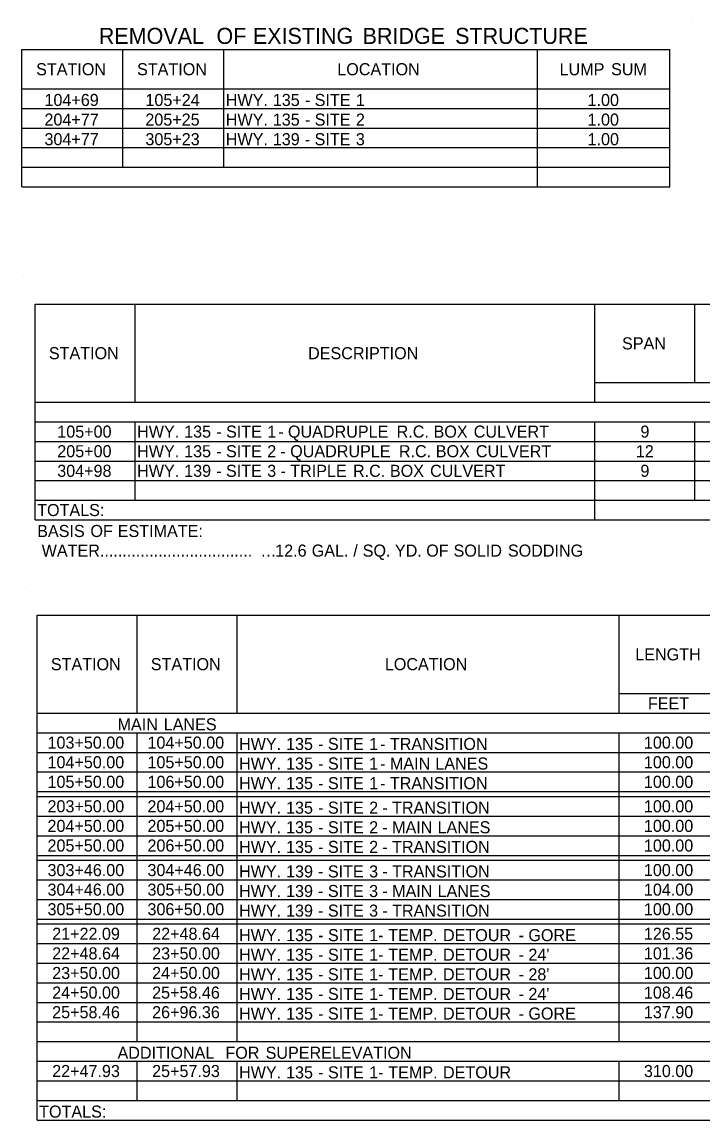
# Model space of a CAD drawing. Extents: x 1955554 to 1962042, y 565952 to 568347.
# Drawn here: x 1958686 to 1959025, y 566455 to 567001 of the extents above; entities that cross this region are included whole.
import ezdxf

# ---------------------------------------------------------------- set-up
doc = ezdxf.new("R2010")
doc.units = 0
doc.layers.add('Default', color=7, linetype='Continuous')
doc.layers.add('R_Border', color=7, linetype='Continuous')

msp = doc.modelspace()

# ---------------------------------------------------------------- linework, layer by layer
at = {"layer": 'Default'}
for p, q in [((1958686.27, 566987.49), (1959008.51, 566987.49)), ((1958686.27, 566919.24), (1958686.27, 566987.49)), ((1958686.27, 566919.24), (1958686.27, 566987.49)), ((1958736.48, 566928.99), (1958736.48, 566987.49)), ((1958786.7, 566928.99), (1958786.7, 566987.49)), ((1958942.7, 566919.24), (1958942.7, 566987.49)), ((1959008.51, 566919.24), (1959008.51, 566987.49)), ((1959008.51, 566919.24), (1959008.51, 566987.49)), ((1958686.27, 566967.99), (1959008.51, 566967.99)), ((1958736.48, 566928.99), (1958736.48, 566967.99)), ((1958786.7, 566928.99), (1958786.7, 566967.99)), ((1958942.7, 566928.99), (1958942.7, 566967.99)), ((1958686.27, 566958.24), (1959008.51, 566958.24)), ((1958942.7, 566958.24), (1959008.51, 566958.24)), ((1958686.27, 566948.49), (1959008.51, 566948.49)), ((1958686.27, 566938.74), (1959008.51, 566938.74)), ((1958686.27, 566928.99), (1958942.7, 566928.99)), ((1958686.27, 566928.99), (1958942.7, 566928.99)), ((1958942.7, 566928.99), (1959008.51, 566928.99)), ((1958686.27, 566919.24), (1959008.51, 566919.24)), ((1958687.02, 566874.57), (1958687.02, 566874.57)), ((1958692.87, 566860.92), (1959581.1, 566860.92)), ((1958692.87, 566753.67), (1958692.87, 566860.92)), ((1958692.87, 566753.67), (1958692.87, 566860.92)), ((1958742.6, 566812.17), (1958742.6, 566860.92)), ((1958971.24, 566812.17), (1958971.24, 566860.92)), ((1959020.96, 566821.92), (1959020.96, 566860.92)), ((1958971.24, 566821.92), (1959369.04, 566821.92)), ((1958692.87, 566812.17), (1959581.1, 566812.17)), ((1958692.87, 566802.42), (1959581.1, 566802.42)), ((1958742.6, 566763.42), (1958742.6, 566802.42)), ((1958742.6, 566763.42), (1958742.6, 566802.42)), ((1958971.24, 566753.67), (1958971.24, 566802.42)), ((1959020.96, 566763.42), (1959020.96, 566802.42)), ((1959020.96, 566763.42), (1959020.96, 566802.42)), ((1958692.87, 566792.67), (1959581.1, 566792.67)), ((1958692.87, 566782.92), (1959581.1, 566782.92)), ((1958692.87, 566773.17), (1959581.1, 566773.17)), ((1958692.87, 566763.42), (1959369.04, 566763.42)), ((1958742.6, 566763.42), (1958971.24, 566763.42)), ((1958971.24, 566763.42), (1959369.04, 566763.42)), ((1958692.87, 566753.67), (1959581.1, 566753.67)), ((1958688, 566719.93), (1958688, 566719.93)), ((1958693.85, 566706.28), (1960133.43, 566706.28)), ((1958693.85, 566455.22), (1958693.85, 566706.28)), ((1958693.85, 566455.22), (1958693.85, 566706.28)), ((1958743.57, 566657.53), (1958743.57, 566706.28)), ((1958793.3, 566657.53), (1958793.3, 566706.28)), ((1958983.42, 566657.53), (1958983.42, 566706.28)), ((1958983.42, 566667.28), (1959033.15, 566667.28)), ((1958693.85, 566657.53), (1960133.43, 566657.53)), ((1958693.85, 566647.78), (1960133.43, 566647.78)), ((1958743.57, 566494.22), (1958743.57, 566647.78)), ((1958743.57, 566494.22), (1958743.57, 566647.78)), ((1958793.3, 566494.22), (1958793.3, 566647.78)), ((1958793.3, 566494.22), (1958793.3, 566647.78)), ((1958983.42, 566494.22), (1958983.42, 566647.78)), ((1958983.42, 566494.22), (1958983.42, 566647.78)), ((1958693.85, 566638.03), (1960133.43, 566638.03)), ((1958693.85, 566628.28), (1960133.43, 566628.28)), ((1958693.85, 566618.53), (1960133.43, 566618.53)), ((1958693.85, 566616.09), (1960133.43, 566616.09)), ((1958693.85, 566606.34), (1960133.43, 566606.34)), ((1958693.85, 566596.59), (1960133.43, 566596.59)), ((1958693.85, 566586.84), (1960133.43, 566586.84)), ((1958693.85, 566584.4), (1960133.43, 566584.4)), ((1958693.85, 566574.65), (1960133.43, 566574.65)), ((1958693.85, 566564.9), (1960133.43, 566564.9)), ((1958693.85, 566555.15), (1960133.43, 566555.15)), ((1958693.85, 566552.72), (1960133.43, 566552.72)), ((1958693.85, 566542.97), (1960133.43, 566542.97)), ((1958693.85, 566533.22), (1960133.43, 566533.22)), ((1958693.85, 566523.47), (1960133.43, 566523.47)), ((1958693.85, 566513.72), (1960133.43, 566513.72)), ((1958693.85, 566503.97), (1960133.43, 566503.97)), ((1958693.85, 566494.22), (1960133.43, 566494.22)), ((1958693.85, 566494.22), (1960133.43, 566494.22)), ((1958693.85, 566484.47), (1960133.43, 566484.47)), ((1958743.57, 566464.97), (1958743.57, 566484.47)), ((1958743.57, 566464.97), (1958743.57, 566484.47)), ((1958793.3, 566464.97), (1958793.3, 566484.47)), ((1958793.3, 566464.97), (1958793.3, 566484.47)), ((1958983.42, 566464.97), (1958983.42, 566484.47)), ((1958983.42, 566464.97), (1958983.42, 566484.47)), ((1958693.85, 566474.72), (1960133.43, 566474.72)), ((1958693.85, 566464.97), (1960133.43, 566464.97)), ((1958693.85, 566455.22), (1960133.43, 566455.22))]:
    msp.add_line(p, q, dxfattribs=at)
at = {"layer": 'R_Border'}
msp.add_line((1959020.08, 567001.23), (1959020.08, 567001.23), dxfattribs=at)

# ---------------------------------------------------------------- texts
at = {"layer": 'Default'}
for s, height, p in [('REMOVAL', 8, (1958724.5, 566990.31)), (' OF', 8, (1958780.06, 566990.31)), (' EXISTING', 8, (1958798.17, 566990.31)), (' BRIDGE', 8, (1958852.77, 566990.31)), (' STRUCTURE', 8, (1958898.8, 566990.31)), ('STATION', 6, (1958693.32, 566974.74)), ('STATION', 6, (1958743.53, 566974.74)), ('LOCATION', 6, (1958843.14, 566974.74)), ('LUMP', 6, (1958953.74, 566974.74)), (' SUM', 6, (1958977.11, 566974.74)), ('104+69', 6, (1958697.47, 566959.44)), ('105+24', 6, (1958747.7, 566959.44)), ('HWY.', 6, (1958787.67, 566959.44)), (' 135', 6, (1958808.83, 566959.44)), (' SITE', 6, (1958829.66, 566959.44)), (' 1', 6, (1958850.17, 566959.44)), ('1.00', 6, (1958967.65, 566959.44)), (' -', 6, (1958824.8, 566959.44)), ('204+77', 6, (1958697.47, 566949.69)), ('205+25', 6, (1958747.66, 566949.69)), ('HWY.', 6, (1958787.67, 566949.69)), (' 135', 6, (1958808.83, 566949.69)), (' -', 6, (1958824.8, 566949.69)), (' SITE', 6, (1958829.66, 566949.69)), (' 2', 6, (1958850.17, 566949.69)), ('1.00', 6, (1958967.65, 566949.69)), ('304+77', 6, (1958697.47, 566939.94)), ('305+23', 6, (1958747.68, 566939.94)), ('HWY.', 6, (1958787.67, 566939.94)), (' 139', 6, (1958808.83, 566939.94)), (' -', 6, (1958824.76, 566939.94)), (' SITE', 6, (1958829.62, 566939.94)), (' 3', 6, (1958850.14, 566939.94)), ('1.00', 6, (1958967.65, 566939.94)), ('SPAN', 6, (1958984.79, 566838.42)), ('STATION', 6, (1958699.67, 566833.54)), ('DESCRIPTION', 6, (1958828.61, 566833.54)), ('105+00', 6, (1958703.84, 566794.54)), ('HWY.', 6, (1958743.57, 566794.54)), (' 135', 6, (1958764.73, 566794.54)), (' SITE', 6, (1958785.56, 566794.54)), (' 1', 6, (1958806.08, 566794.54)), (' QUADRUPLE', 6, (1958816.38, 566794.54)), (' R.C.', 6, (1958870.44, 566794.54)), (' BOX', 6, (1958888.8, 566794.54)), (' CULVERT', 6, (1958908.78, 566794.54)), ('9', 6, (1958993.95, 566794.54)), (' -', 6, (1958780.7, 566794.54)), (' -', 6, (1958811.52, 566794.54)), ('205+00', 6, (1958703.84, 566784.79)), ('HWY.', 6, (1958743.57, 566784.79)), (' 135', 6, (1958764.73, 566784.79)), (' SITE', 6, (1958785.56, 566784.79)), (' 2', 6, (1958806.08, 566784.79)), (' QUADRUPLE', 6, (1958817.48, 566784.79)), (' R.C.', 6, (1958871.54, 566784.79)), (' BOX', 6, (1958889.9, 566784.79)), (' CULVERT', 6, (1958909.88, 566784.79)), ('12', 6, (1958991.66, 566784.79)), (' -', 6, (1958780.7, 566784.79)), (' -', 6, (1958812.62, 566784.79)), ('304+98', 6, (1958703.82, 566775.04)), ('HWY.', 6, (1958743.57, 566775.04)), (' 139', 6, (1958764.73, 566775.04)), (' -', 6, (1958780.67, 566775.04)), (' SITE', 6, (1958785.52, 566775.04)), (' 3', 6, (1958806.04, 566775.04)), (' -', 6, (1958812.65, 566775.04)), (' TRIPLE', 6, (1958817.5, 566775.04)), (' R.C.', 6, (1958848.73, 566775.04)), (' BOX', 6, (1958867.1, 566775.04)), (' CULVERT', 6, (1958887.08, 566775.04)), ('9', 6, (1958993.95, 566775.04)), ('TOTALS:', 6, (1958693.85, 566755.54)), ('BASIS', 6, (1958693.85, 566745.12)), (' OF', 6, (1958718.11, 566745.12)), (' ESTIMATE:', 6, (1958731.7, 566745.12)), (' WATER..................................', 6, (1958693.85, 566735.37)), ('12.6', 6, (1958812.26, 566735.37)), (' GAL.', 6, (1958828.19, 566735.37)), (' /', 6, (1958848.89, 566735.37)), (' SQ.', 6, (1958853.55, 566735.37)), (' YD.', 6, (1958869.59, 566735.37)), (' OF', 6, (1958885.16, 566735.37)), (' SOLID', 6, (1958898.75, 566735.37)), (' SODDING', 6, (1958925.78, 566735.37)), ('…', 6, (1958804.86, 566735.37)), ('LENGTH', 6, (1958991.37, 566683.78)), ('STATION', 6, (1958700.65, 566678.9)), ('STATION', 6, (1958750.37, 566678.9)), ('LOCATION', 6, (1958866.8, 566678.9)), ('FEET', 6, (1958997.65, 566659.4)), ('MAIN', 6, (1958733.82, 566648.98)), (' LANES', 6, (1958754.57, 566648.98)), ('103+50.00', 6, (1958698.99, 566639.9)), ('104+50.00', 6, (1958748.71, 566639.9)), ('100.00', 6, (1958995.67, 566639.9)), ('HWY.', 6, (1958794.27, 566639.23)), (' 135', 6, (1958815.43, 566639.23)), (' -', 6, (1958831.4, 566639.23)), (' SITE', 6, (1958836.26, 566639.23)), (' 1', 6, (1958856.77, 566639.23)), (' -', 6, (1958862.22, 566639.23)), (' TRANSITION', 6, (1958867.08, 566639.23)), ('104+50.00', 6, (1958698.99, 566630.15)), ('105+50.00', 6, (1958748.71, 566630.15)), ('HWY.', 6, (1958794.27, 566629.48)), (' 135', 6, (1958815.43, 566629.48)), (' SITE', 6, (1958836.26, 566629.48)), (' 1', 6, (1958856.77, 566629.48)), (' MAIN', 6, (1958867.08, 566629.48)), (' LANES', 6, (1958889.68, 566629.48)), ('100.00', 6, (1958995.67, 566630.15)), (' -', 6, (1958831.4, 566629.48)), (' -', 6, (1958862.22, 566629.48)), ('105+50.00', 6, (1958698.99, 566620.4)), ('106+50.00', 6, (1958748.71, 566620.4)), ('HWY.', 6, (1958794.27, 566619.73)), (' 135', 6, (1958815.43, 566619.73)), (' SITE', 6, (1958836.26, 566619.73)), (' 1', 6, (1958856.77, 566619.73)), (' TRANSITION', 6, (1958867.08, 566619.73)), ('100.00', 6, (1958995.67, 566620.4)), (' -', 6, (1958831.4, 566619.73)), (' -', 6, (1958862.22, 566619.73)), ('203+50.00', 6, (1958698.99, 566608.22)), ('204+50.00', 6, (1958748.71, 566608.22)), ('HWY.', 6, (1958794.27, 566607.54)), (' 135', 6, (1958815.43, 566607.54)), (' SITE', 6, (1958836.26, 566607.54)), (' 2', 6, (1958856.77, 566607.54)), (' TRANSITION', 6, (1958868.17, 566607.54)), ('100.00', 6, (1958995.67, 566608.22)), (' -', 6, (1958831.4, 566607.54)), (' -', 6, (1958863.32, 566607.54)), ('204+50.00', 6, (1958698.99, 566598.47)), ('205+50.00', 6, (1958748.71, 566598.47)), ('HWY.', 6, (1958794.27, 566597.79)), (' 135', 6, (1958815.43, 566597.79)), (' SITE', 6, (1958836.26, 566597.79)), (' 2', 6, (1958856.77, 566597.79)), (' MAIN', 6, (1958868.17, 566597.79)), (' LANES', 6, (1958890.77, 566597.79)), ('100.00', 6, (1958995.67, 566598.47)), (' -', 6, (1958831.4, 566597.79)), (' -', 6, (1958863.32, 566597.79)), ('205+50.00', 6, (1958698.99, 566588.72)), ('206+50.00', 6, (1958748.71, 566588.72)), ('HWY.', 6, (1958794.27, 566588.04)), (' 135', 6, (1958815.43, 566588.04)), (' SITE', 6, (1958836.26, 566588.04)), (' 2', 6, (1958856.77, 566588.04)), (' TRANSITION', 6, (1958868.17, 566588.04)), ('100.00', 6, (1958995.67, 566588.72)), (' -', 6, (1958831.4, 566588.04)), (' -', 6, (1958863.32, 566588.04)), ('303+46.00', 6, (1958698.99, 566576.53)), ('304+46.00', 6, (1958748.71, 566576.53)), ('HWY.', 6, (1958794.27, 566575.85)), (' 139', 6, (1958815.43, 566575.85)), (' SITE', 6, (1958836.22, 566575.85)), (' 3', 6, (1958856.74, 566575.85)), (' TRANSITION', 6, (1958868.2, 566575.85)), ('100.00', 6, (1958995.67, 566576.53)), (' -', 6, (1958831.36, 566575.85)), (' -', 6, (1958863.34, 566575.85)), ('304+46.00', 6, (1958698.99, 566566.78)), ('305+50.00', 6, (1958748.71, 566566.78)), ('HWY.', 6, (1958794.27, 566566.1)), (' 139', 6, (1958815.43, 566566.1)), (' SITE', 6, (1958836.22, 566566.1)), (' 3', 6, (1958856.74, 566566.1)), (' MAIN', 6, (1958868.2, 566566.1)), (' LANES', 6, (1958890.8, 566566.1)), ('104.00', 6, (1958995.67, 566566.78)), (' -', 6, (1958831.36, 566566.1)), (' -', 6, (1958863.34, 566566.1)), ('305+50.00', 6, (1958698.99, 566557.03)), ('306+50.00', 6, (1958748.71, 566557.03)), ('HWY.', 6, (1958794.27, 566556.35)), (' 139', 6, (1958815.43, 566556.35)), (' -', 6, (1958831.36, 566556.35)), (' SITE', 6, (1958836.22, 566556.35)), (' 3', 6, (1958856.74, 566556.35)), (' -', 6, (1958863.34, 566556.35)), (' TRANSITION', 6, (1958868.2, 566556.35)), ('100.00', 6, (1958995.67, 566557.03)), ('21+22.09', 6, (1958701.3, 566544.84)), ('22+48.64', 6, (1958751.05, 566544.84)), ('HWY.', 6, (1958794.27, 566544.17)), (' 135', 6, (1958815.43, 566544.17)), (' SITE', 6, (1958836.26, 566544.17)), (' 1-', 6, (1958856.77, 566544.17)), (' TEMP.', 6, (1958866.29, 566544.17)), (' DETOUR', 6, (1958893.5, 566544.17)), (' GORE', 6, (1958935.97, 566544.17)), ('126.55', 6, (1958995.64, 566544.84)), (' -', 6, (1958831.4, 566544.17)), (' -', 6, (1958931.12, 566544.17)), ('22+48.64', 6, (1958701.32, 566535.09)), ('23+50.00', 6, (1958751.04, 566535.09)), ('HWY.', 6, (1958794.27, 566534.42)), (' 135', 6, (1958815.43, 566534.42)), (' -', 6, (1958831.4, 566534.42)), (' SITE', 6, (1958836.26, 566534.42)), (' 1-', 6, (1958856.77, 566534.42)), (' TEMP.', 6, (1958866.29, 566534.42)), (' DETOUR', 6, (1958893.5, 566534.42)), (' -', 6, (1958931.12, 566534.42)), (" 24'", 6, (1958935.97, 566534.42)), ('101.36', 6, (1958995.66, 566535.09)), ('23+50.00', 6, (1958701.32, 566525.34)), ('24+50.00', 6, (1958751.04, 566525.34)), ('100.00', 6, (1958995.67, 566525.34)), ('HWY.', 6, (1958794.27, 566524.67)), (' 135', 6, (1958815.43, 566524.67)), (' -', 6, (1958831.4, 566524.67)), (' SITE', 6, (1958836.26, 566524.67)), (' 1-', 6, (1958856.77, 566524.67)), (' TEMP.', 6, (1958866.29, 566524.67)), (' DETOUR', 6, (1958893.5, 566524.67)), (' -', 6, (1958931.12, 566524.67)), (" 28'", 6, (1958935.97, 566524.67)), ('24+50.00', 6, (1958701.32, 566515.59)), ('25+58.46', 6, (1958751.03, 566515.59)), ('HWY.', 6, (1958794.27, 566514.92)), (' 135', 6, (1958815.43, 566514.92)), (' SITE', 6, (1958836.26, 566514.92)), (' 1-', 6, (1958856.77, 566514.92)), (' TEMP.', 6, (1958866.29, 566514.92)), (' DETOUR', 6, (1958893.5, 566514.92)), (" 24'", 6, (1958935.97, 566514.92)), ('108.46', 6, (1958995.66, 566515.59)), (' -', 6, (1958831.4, 566514.92)), (' -', 6, (1958931.12, 566514.92)), ('25+58.46', 6, (1958701.31, 566505.84)), ('26+96.36', 6, (1958751.03, 566505.84)), ('HWY.', 6, (1958794.27, 566505.17)), (' 135', 6, (1958815.43, 566505.17)), (' SITE', 6, (1958836.26, 566505.17)), (' 1-', 6, (1958856.77, 566505.17)), (' TEMP.', 6, (1958866.29, 566505.17)), (' DETOUR', 6, (1958893.5, 566505.17)), (' GORE', 6, (1958935.97, 566505.17)), ('137.90', 6, (1958995.67, 566505.84)), (' -', 6, (1958831.4, 566505.17)), (' -', 6, (1958931.12, 566505.17)), ('ADDITIONAL', 6, (1958733.82, 566485.67)), (' FOR', 6, (1958785.26, 566485.67)), (' SUPERELEVATION', 6, (1958805.25, 566485.67)), ('22+47.93', 6, (1958701.31, 566476.59)), ('25+57.93', 6, (1958751.03, 566476.59)), (' 135', 6, (1958815.43, 566475.92)), (' SITE', 6, (1958836.26, 566475.92)), (' DETOUR', 6, (1958893.5, 566475.92)), ('310.00', 6, (1958995.67, 566476.59)), ('HWY.', 6, (1958794.27, 566475.92)), (' -', 6, (1958831.4, 566475.92)), (' 1-', 6, (1958856.77, 566475.92)), (' TEMP.', 6, (1958866.29, 566475.92)), ('TOTALS:', 6, (1958694.82, 566456.42))]:
    msp.add_text(s, height=height, dxfattribs=at).set_placement(p)

doc.saveas('drawing.dxf')
